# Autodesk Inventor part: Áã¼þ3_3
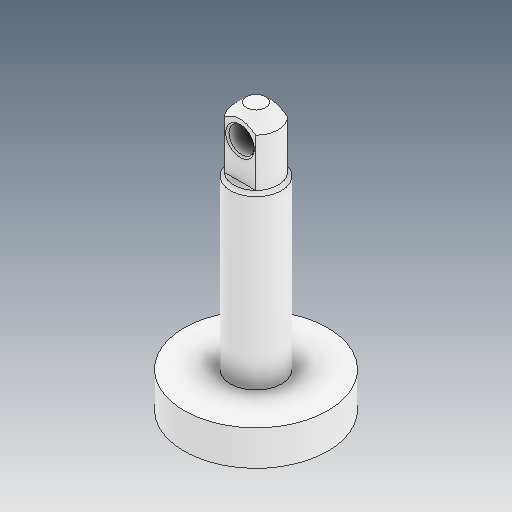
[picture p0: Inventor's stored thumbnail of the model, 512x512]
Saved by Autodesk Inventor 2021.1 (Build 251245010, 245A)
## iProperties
Created: 2021-05
Part Number: Áã¼þ3_3
Material: Ogólny
Document SubType Name: Modeling
Designer: user
Density: 1 g/cm^3
Appearance: Domyślna
Author: user
Revision Number: ÈÎºÎ
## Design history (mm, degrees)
feature "ÊäÈë1"
node "Bryła1"
